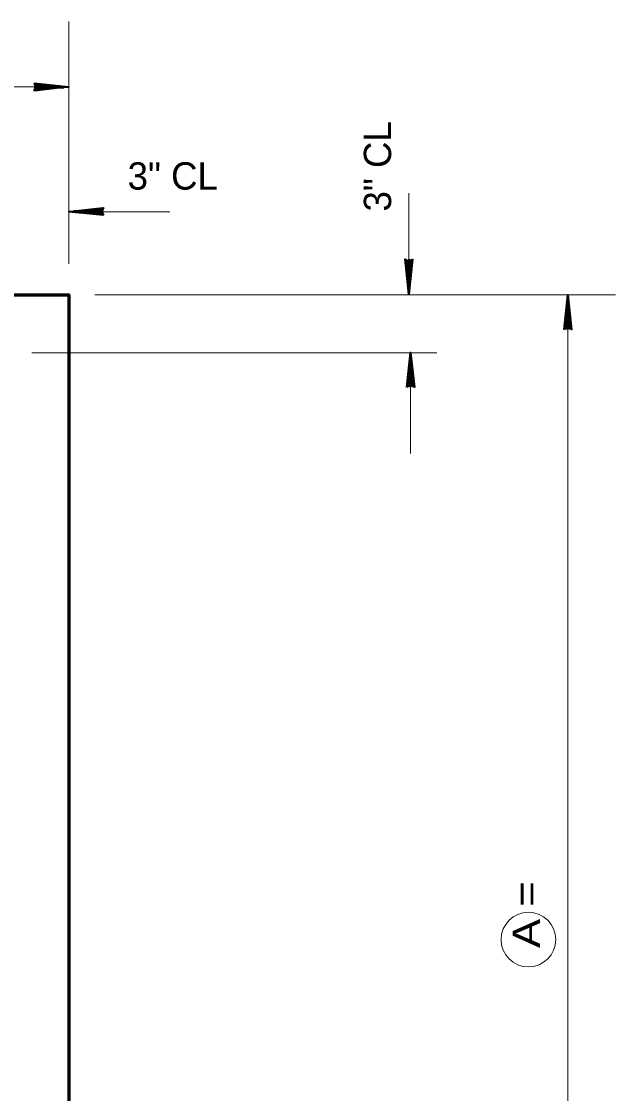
# Model space of a CAD drawing. Extents: x 3.64 to 6.84, y -0.8 to 1.19.
# Drawn here: x 5.2545 to 5.4356, y 0.0313 to 0.358 of the extents above; entities that cross this region are included whole.
import ezdxf

# ---------------------------------------------------------------- set-up
doc = ezdxf.new("R2010")
doc.units = 0
doc.header["$LTSCALE"] = 0.0033
doc.layers.add('1', color=7, linetype='Continuous', lineweight=40)

msp = doc.modelspace()

# ---------------------------------------------------------------- linework, layer by layer
at = {"layer": '1', "lineweight": 13}
for p, q in [((5.268917, 0.284167), (5.268917, 0.358)), ((5.1025, 0.338083), (5.268917, 0.338083)), ((5.372583, 0.284833), (5.372583, 0.305667)), ((5.278833, 0.3), (5.299667, 0.3)), ((5.276833, 0.274667), (5.435583, 0.274667)), ((5.421, -0.141167), (5.421, 0.274583)), ((5.268917, 0.189583), (5.268917, 0.262417)), ((5.257667, 0.257), (5.381083, 0.257)), ((5.373083, 0.226333), (5.373083, 0.247167))]:
    msp.add_line(p, q, dxfattribs=at)
at = {"layer": '1', "lineweight": 35}
for p, q in [((5.258333, 0.338083), (5.268917, 0.338083)), ((5.2585, 0.337417), (5.265833, 0.338167)), ((5.258583, 0.339083), (5.266417, 0.338167)), ((5.258583, 0.339083), (5.266417, 0.338167)), ((5.258583, 0.339), (5.266417, 0.338167)), ((5.258583, 0.338917), (5.266417, 0.338083)), ((5.258583, 0.338917), (5.266417, 0.337917)), ((5.258583, 0.33725), (5.265917, 0.338083)), ((5.258583, 0.337167), (5.265917, 0.337917)), ((5.258583, 0.337), (5.265917, 0.337833)), ((5.27925, 0.301083), (5.271917, 0.30025)), ((5.27925, 0.300917), (5.271917, 0.300167)), ((5.27925, 0.300833), (5.271917, 0.3)), ((5.279333, 0.300667), (5.272, 0.299917)), ((5.2795, 0.3), (5.268917, 0.3)), ((5.27925, 0.299167), (5.271417, 0.300167)), ((5.27925, 0.299167), (5.271417, 0.3)), ((5.27925, 0.299), (5.271417, 0.299917)), ((5.27925, 0.299), (5.271417, 0.299917)), ((5.27925, 0.299083), (5.271417, 0.299917)), ((5.3715, 0.28525), (5.372333, 0.277917)), ((5.371667, 0.28525), (5.372417, 0.277917)), ((5.37175, 0.28525), (5.372583, 0.277917)), ((5.371917, 0.285333), (5.372667, 0.278)), ((5.373417, 0.28525), (5.372417, 0.277417)), ((5.372583, 0.2855), (5.372583, 0.274917)), ((5.373417, 0.28525), (5.372583, 0.277417)), ((5.373583, 0.28525), (5.372667, 0.277417)), ((5.373583, 0.28525), (5.372667, 0.277417)), ((5.3735, 0.28525), (5.372667, 0.277417)), ((5.421, 0.264083), (5.421, 0.274667)), ((5.42, 0.264333), (5.420917, 0.272167)), ((5.42, 0.264333), (5.420917, 0.272167)), ((5.420083, 0.264333), (5.420917, 0.272167)), ((5.420167, 0.264333), (5.421, 0.272167)), ((5.420167, 0.264333), (5.421167, 0.272167)), ((5.421667, 0.26425), (5.420917, 0.271583)), ((5.421833, 0.264333), (5.421, 0.271667)), ((5.421917, 0.264333), (5.421167, 0.271667)), ((5.422083, 0.264333), (5.42125, 0.271667)), ((5.373083, 0.2465), (5.373083, 0.257083)), ((5.372083, 0.24675), (5.373, 0.254583)), ((5.372083, 0.24675), (5.373, 0.254583)), ((5.372167, 0.24675), (5.373, 0.254583)), ((5.37225, 0.24675), (5.373083, 0.254583)), ((5.37225, 0.24675), (5.37325, 0.254583)), ((5.37375, 0.246667), (5.373, 0.254)), ((5.373917, 0.24675), (5.373083, 0.254083)), ((5.374, 0.24675), (5.37325, 0.254083)), ((5.374167, 0.24675), (5.373333, 0.254083))]:
    msp.add_line(p, q, dxfattribs=at)
for points in [[(5.258333, 0.339167), (5.268917, 0.338083), (5.258333, 0.336917), (5.258917, 0.338083)], [(5.259083, 0.338167), (5.26375, 0.33825), (5.26375, 0.338167), (5.262833, 0.338167), (5.259083, 0.33825), (5.262083, 0.338333), (5.258917, 0.338417), (5.261167, 0.3385), (5.258917, 0.338583), (5.262417, 0.338333), (5.267083, 0.338167), (5.266167, 0.337917), (5.267417, 0.337917), (5.259083, 0.337917), (5.2615, 0.33775), (5.258917, 0.33775), (5.26425, 0.338167), (5.258917, 0.3375)], [(5.2795, 0.298917), (5.268917, 0.3), (5.2795, 0.301167), (5.278917, 0.3)], [(5.27875, 0.299917), (5.274083, 0.299833), (5.274083, 0.299917), (5.275, 0.299917), (5.27875, 0.299833), (5.27575, 0.29975), (5.278917, 0.299667), (5.276667, 0.299583), (5.278917, 0.2995), (5.275417, 0.29975), (5.27075, 0.299917), (5.271667, 0.300167), (5.270417, 0.300167), (5.27875, 0.300167), (5.276333, 0.300333), (5.278917, 0.300333), (5.273583, 0.299917), (5.278917, 0.300583)], [(5.373667, 0.2855), (5.372583, 0.274917), (5.371417, 0.2855), (5.372583, 0.284917)], [(5.372667, 0.28475), (5.37275, 0.280083), (5.372667, 0.280083), (5.372667, 0.281), (5.37275, 0.28475), (5.372833, 0.28175), (5.372917, 0.284917), (5.373, 0.282667), (5.373083, 0.284917), (5.372833, 0.281417), (5.372667, 0.27675), (5.372417, 0.277667), (5.372417, 0.276417), (5.372417, 0.28475), (5.37225, 0.282333), (5.37225, 0.284917), (5.372667, 0.279583), (5.372, 0.284917)], [(5.419917, 0.264083), (5.421, 0.274667), (5.422167, 0.264083), (5.421, 0.264667)], [(5.420917, 0.264833), (5.420833, 0.2695), (5.420917, 0.2695), (5.420917, 0.268583), (5.420833, 0.264833), (5.42075, 0.267833), (5.420667, 0.264667), (5.420583, 0.266917), (5.4205, 0.264667), (5.42075, 0.268167), (5.420917, 0.272833), (5.421167, 0.271917), (5.421167, 0.273167), (5.421167, 0.264833), (5.421333, 0.26725), (5.421333, 0.264667), (5.420917, 0.27), (5.421583, 0.264667)], [(5.372, 0.2465), (5.373083, 0.257083), (5.37425, 0.2465), (5.373083, 0.247083)], [(5.373, 0.24725), (5.372917, 0.251917), (5.373, 0.251917), (5.373, 0.251), (5.372917, 0.24725), (5.372833, 0.25025), (5.37275, 0.247083), (5.372667, 0.249333), (5.372583, 0.247083), (5.372833, 0.250583), (5.373, 0.25525), (5.37325, 0.254333), (5.37325, 0.255583), (5.37325, 0.24725), (5.373417, 0.249667), (5.373417, 0.247083), (5.373, 0.252417), (5.373667, 0.247083)]]:
    msp.add_lwpolyline(points, close=True, dxfattribs=at)
for points in [[(5.259083, 0.338167), (5.258667, 0.338917), (5.258917, 0.338667), (5.259083, 0.338333), (5.259333, 0.338417), (5.259167, 0.33875), (5.259, 0.338), (5.258833, 0.3375), (5.258583, 0.337083)], [(5.27875, 0.299917), (5.279167, 0.299167), (5.278917, 0.299417), (5.27875, 0.29975), (5.2785, 0.299667), (5.278667, 0.299333), (5.278833, 0.300083), (5.279, 0.300583), (5.27925, 0.301)], [(5.372667, 0.28475), (5.373417, 0.285167), (5.373167, 0.284917), (5.372833, 0.28475), (5.372917, 0.2845), (5.37325, 0.284667), (5.3725, 0.284833), (5.372, 0.285), (5.371583, 0.28525)], [(5.420917, 0.264833), (5.420167, 0.264417), (5.420417, 0.264667), (5.42075, 0.264833), (5.420667, 0.265083), (5.420333, 0.264917), (5.421083, 0.26475), (5.421583, 0.264583), (5.422, 0.264333)], [(5.373, 0.24725), (5.37225, 0.246833), (5.3725, 0.247083), (5.372833, 0.24725), (5.37275, 0.2475), (5.372417, 0.247333), (5.373167, 0.247167), (5.373667, 0.247), (5.374083, 0.24675)]]:
    msp.add_lwpolyline(points, dxfattribs=at)
at = {"layer": '1', "lineweight": 60}
msp.add_lwpolyline([(5.018917, -0.058667), (5.10225, -0.058667), (5.10225, 0.274667), (5.268917, 0.274667), (5.268917, -0.058667), (5.35225, -0.058667)], dxfattribs=at)
at = {"layer": '1', "lineweight": 13}
msp.add_circle((5.409, 0.078167), 0.008333, dxfattribs=at)

# ---------------------------------------------------------------- texts
at = {"layer": '1'}
msp.add_text('3" CL', height=0.008334, rotation=90, dxfattribs=at).set_placement((5.367167, 0.300083))
msp.add_text('3" CL', height=0.008334, dxfattribs=at).set_placement((5.286833, 0.30675))
at = {"layer": '1', "width": 1.2}
msp.add_text('A =      ', height=0.008334, rotation=90, dxfattribs=at).set_placement((5.412583, 0.075583))

doc.saveas('drawing.dxf')
